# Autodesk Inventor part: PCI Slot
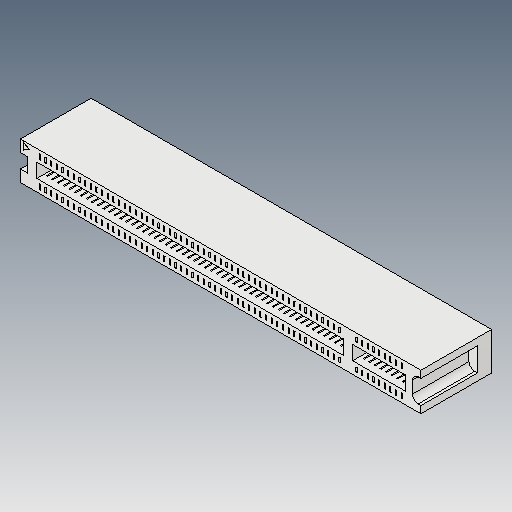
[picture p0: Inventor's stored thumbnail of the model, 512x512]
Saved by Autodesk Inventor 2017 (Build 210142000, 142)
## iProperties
Created: 2005-12
Part Number: PCI Slot
Material: Generic
Document SubType Name: Modeling
Designer: DanielSeverino
Density: 1 g/cm^3
Appearance: Default
Author: DanielSeverino
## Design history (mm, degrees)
feature "Solid1"
body "Solid2"
